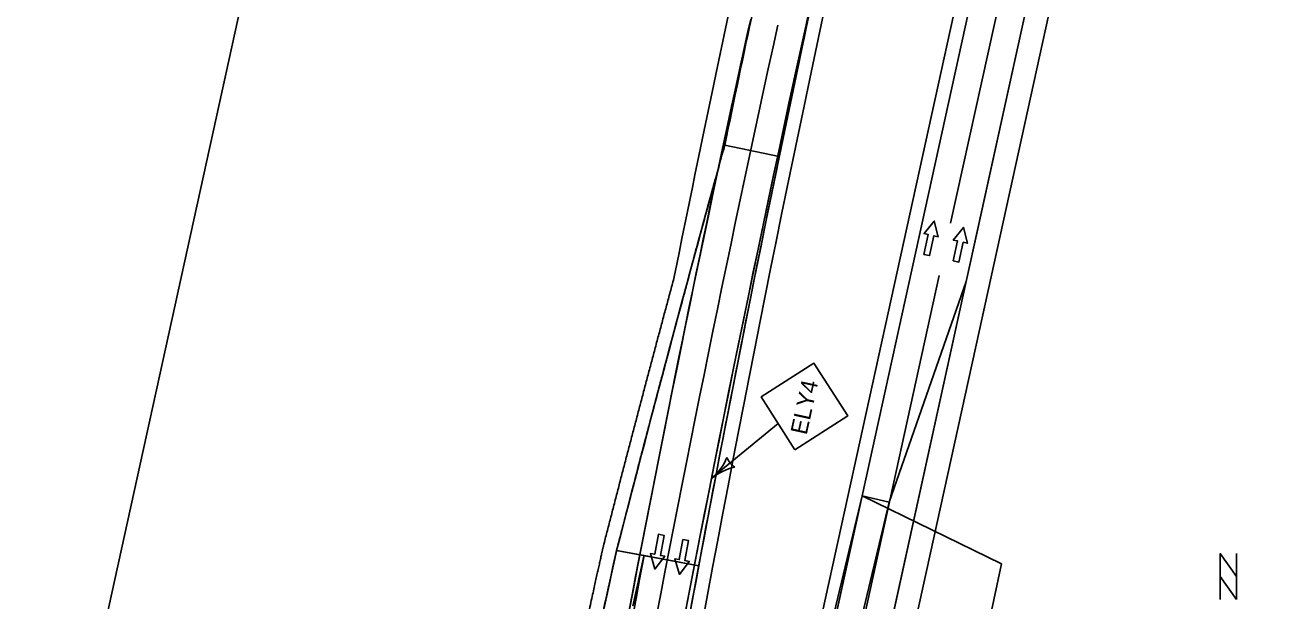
# Model space of a CAD drawing. Extents: x 14104283 to 14120882, y 8635219 to 8671666.
# Drawn here: x 14107791 to 14108331, y 8640647 to 8640895 of the extents above; entities that cross this region are included whole.
import ezdxf

# ---------------------------------------------------------------- set-up
doc = ezdxf.new("R2010")
doc.units = 0
for name, color, linetype in [('Cell', 7, 'Continuous'), ('dsnCellsNorthArrow', 7, 'Continuous'), ('dsnNonPlotable', 7, 'Continuous'), ('dsnPaintExistingBrokenLaneLineWhite', 7, 'Continuous'), ('dsnPaintExistingEdgeLineLeftYellow', 7, 'Continuous'), ('dsnPaintExistingEdgeLineRightWhite', 7, 'Continuous'), ('dsnPaintPlaceBrokenLaneLineWhite', 7, 'Continuous'), ('dsnPaintPlaceEdgeLineLeftYellow', 7, 'Continuous'), ('dsnPaintPlaceEdgeLineRightWhite', 7, 'Continuous'), ('dsnShadingPaved', 7, 'Continuous'), ('dsnStdLabel', 7, 'Continuous'), ('dsnStgShadingPrevPav', 7, 'Continuous'), ('dsnTapeRemoveChannelizingWhite', 7, 'Continuous'), ('dsnTapeRemoveChannelizingYellow', 7, 'Continuous'), ('Text', 7, 'Continuous')]:
    doc.layers.add(name, color=color, linetype=linetype)

msp = doc.modelspace()

# ---------------------------------------------------------------- linework, layer by layer
at = {"layer": 'Cell'}
for points in [[(14108180.75, 8640796.06), (14108178.31, 8640796.6), (14108180.19, 8640805.14), (14108178.36, 8640805.55), (14108182.76, 8640810.98), (14108184.46, 8640804.2), (14108182.63, 8640804.61)], [(14108193.37, 8640793.29), (14108190.92, 8640793.83), (14108192.81, 8640802.37), (14108190.98, 8640802.78), (14108195.38, 8640808.21), (14108197.08, 8640801.43), (14108195.25, 8640801.83)], [(14108063.89, 8640675.97), (14108066.35, 8640675.52), (14108064.79, 8640666.91), (14108066.63, 8640666.58), (14108062.44, 8640660.99), (14108060.48, 8640667.69), (14108062.33, 8640667.36)], [(14108074.46, 8640673.7), (14108076.92, 8640673.25), (14108075.36, 8640664.64), (14108077.2, 8640664.31), (14108073.01, 8640658.72), (14108071.05, 8640665.43), (14108072.9, 8640665.09)]]:
    msp.add_lwpolyline(points, close=True, dxfattribs=at)
for points in [[(14108182.63, 8640804.61), (14108184.46, 8640804.2), (14108182.76, 8640810.98), (14108178.36, 8640805.55), (14108180.19, 8640805.14), (14108178.31, 8640796.6), (14108180.75, 8640796.06), (14108182.63, 8640804.61)], [(14108195.25, 8640801.83), (14108197.08, 8640801.43), (14108195.38, 8640808.21), (14108190.98, 8640802.78), (14108192.81, 8640802.37), (14108190.92, 8640793.83), (14108193.37, 8640793.29), (14108195.25, 8640801.83)], [(14108062.33, 8640667.36), (14108060.48, 8640667.69), (14108062.44, 8640660.99), (14108066.63, 8640666.58), (14108064.79, 8640666.91), (14108066.35, 8640675.52), (14108063.89, 8640675.97), (14108062.33, 8640667.36)], [(14108072.9, 8640665.09), (14108071.05, 8640665.43), (14108073.01, 8640658.72), (14108077.2, 8640664.31), (14108075.36, 8640664.64), (14108076.92, 8640673.25), (14108074.46, 8640673.7), (14108072.9, 8640665.09)]]:
    msp.add_lwpolyline(points, dxfattribs=at)
at = {"layer": 'dsnCellsNorthArrow'}
msp.add_lwpolyline([(14108313, 8640647.95), (14108305.96, 8640657.81), (14108305.96, 8640667.66), (14108313, 8640657.81)], close=True, dxfattribs=at)
msp.add_lwpolyline([(14108305.96, 8640647.95), (14108305.96, 8640667.66), (14108313, 8640657.81), (14108313, 8640667.66)], dxfattribs=at)
at = {"layer": 'dsnNonPlotable'}
msp.add_lwpolyline([(14107651.31, 8639844.94), (14107987.7, 8641375.92), (14108480.93, 8641267.54), (14108144.54, 8639736.56)], close=True, dxfattribs=at)
at = {"layer": 'dsnPaintExistingBrokenLaneLineWhite'}
msp.add_line((14108189.82, 8640810.08), (14108306.37, 8641340.66), dxfattribs=at)
msp.add_arc((14117394.14, 8638857.08), 9500, 167.610212, 171.325989, dxfattribs=at)
at = {"layer": 'dsnPaintExistingEdgeLineLeftYellow'}
msp.add_line((14108151.72, 8640692.57), (14108199.55, 8640910.32), dxfattribs=at)
at = {"layer": 'dsnPaintExistingEdgeLineRightWhite'}
for p, q in [((14108201.57, 8640807.63), (14108723.98, 8643185.75)), ((14108196.58, 8640784.95), (14108201.57, 8640807.63))]:
    msp.add_line(p, q, dxfattribs=at)
for centre, radius, start, end in [((14117394.14, 8638857.08), 9512, 167.610212, 168.003119), ((14117245.13, 8638308.71), 9497.18, 164.578206, 165.609485), ((14117342.69, 8638609.63), 9522.13, 167.509575, 168.915877)]:
    msp.add_arc(centre, radius, start, end, dxfattribs=at)
at = {"layer": 'dsnPaintPlaceBrokenLaneLineWhite'}
msp.add_line((14108099.08, 8640397.01), (14108184.86, 8640787.53), dxfattribs=at)
at = {"layer": 'dsnPaintPlaceEdgeLineLeftYellow'}
msp.add_line((14108129.2, 8640590.05), (14108151.72, 8640692.57), dxfattribs=at)
msp.add_arc((14117502.5, 8638839.63), 9597.75, 167.26751, 171.3206, dxfattribs=at)
at = {"layer": 'dsnPaintPlaceEdgeLineRightWhite'}
msp.add_line((14108110.8, 8640394.44), (14108196.58, 8640784.95), dxfattribs=at)
at = {"layer": 'dsnShadingPaved'}
for p, q in [((14108723.98, 8643185.75), (14108196.58, 8640784.95)), ((14108151.72, 8640692.57), (14108294.65, 8641343.23)), ((14108196.58, 8640784.95), (14108163.38, 8640689.76)), ((14108163.38, 8640689.76), (14108151.72, 8640692.57))]:
    msp.add_line(p, q, dxfattribs=at)
msp.add_lwpolyline([(14108083.12, 8640400.52), (14108129.2, 8640590.05), (14108151.72, 8640692.57), (14108163.38, 8640689.76), (14108196.58, 8640784.95), (14108110.8, 8640394.44)], close=True, dxfattribs=at)
for centre, radius, start, end in [((14117502.5, 8638839.63), 9597.75, 167.266653, 171.3206), ((14117394.14, 8638857.08), 9512, 167.610212, 171.325989), ((14117394.14, 8638857.08), 9500, 167.610212, 171.325989), ((14117394.14, 8638857.08), 9500, 167.610212, 171.325989), ((14117502.5, 8638839.63), 9621.75, 168.048489, 169.460498), ((14117245.13, 8638308.71), 9497.18, 164.591267, 165.609485), ((14117342.69, 8638609.63), 9522.13, 167.509575, 168.915877)]:
    msp.add_arc(centre, radius, start, end, dxfattribs=at)
at = {"layer": 'dsnStdLabel'}
msp.add_line((14108115.47, 8640723.79), (14108086.85, 8640700.1), dxfattribs=at)
msp.add_lwpolyline([(14108122.75, 8640712.41), (14108145.49, 8640726.96), (14108130.94, 8640749.71), (14108108.2, 8640735.16)], close=True, dxfattribs=at)
for centre, radius, start, end in [((14108072.21, 8640717.78), 22.95, 309.6084, 337.6796), ((14108101.67, 8640712.36), 8.86, 201.8742, 237.3427), ((14108101.48, 8640682.41), 22.95, 101.5372, 129.6085)]:
    msp.add_arc(centre, radius, start, end, dxfattribs=at)
at = {"layer": 'dsnStgShadingPrevPav'}
for p, q in [((14108092.51, 8640843.67), (14108116.01, 8640838.82)), ((14108116.01, 8640838.82), (14108092.51, 8640843.67)), ((14108045.92, 8640669.04), (14108057.72, 8640666.84)), ((14108081.31, 8640662.43), (14108045.92, 8640669.04)), ((14108057.72, 8640666.84), (14108081.31, 8640662.43))]:
    msp.add_line(p, q, dxfattribs=at)
msp.add_lwpolyline([(14108081.5, 8640400.87), (14108123.34, 8640591.33), (14108126.55, 8640605.98), (14108216.67, 8641016.2), (14108268.16, 8641250.61), (14108382.95, 8641773.15), (14108422.02, 8641764.57), (14108309.38, 8641251.8), (14108270.22, 8641073.55), (14108265.93, 8641054.01), (14108255.74, 8641007.62), (14108202.1, 8640763.44), (14108120.56, 8640392.29)], close=True, dxfattribs=at)
for radius, start, end in [(9522, 167.610212, 168.688952), (9512, 167.610212, 168.328257), (9512, 167.610212, 168.328257), (9488, 167.610212, 172.222077), (9482, 167.610212, 172.222077), (9488, 167.610212, 168.328257), (9488, 168.328257, 169.413861), (9512, 169.413861, 172.222077), (9488, 169.413861, 172.222077), (9512, 169.413861, 170.574102)]:
    msp.add_arc((14117407.82, 8638919.35), radius, start, end, dxfattribs=at)
for points, degree in [([(14108045.92, 8640669.04), (14108046.67, 8640671.96), (14108048.17, 8640677.8), (14108050.43, 8640686.55), (14108052.7, 8640695.31), (14108054.98, 8640704.06), (14108057.26, 8640712.8), (14108059.55, 8640721.55), (14108061.85, 8640730.29), (14108064.16, 8640739.03), (14108066.48, 8640747.76), (14108068.81, 8640756.5), (14108071.14, 8640765.23), (14108073.48, 8640773.95), (14108075.83, 8640782.68), (14108078.19, 8640791.4), (14108080.55, 8640800.12), (14108082.93, 8640808.84), (14108085.31, 8640817.55), (14108087.7, 8640826.26), (14108090.1, 8640834.97), (14108091.7, 8640840.77), (14108092.51, 8640843.67)], 3), ([(14108045.92, 8640669.04), (14108046.67, 8640671.96), (14108048.17, 8640677.8), (14108050.43, 8640686.55), (14108052.7, 8640695.31), (14108054.98, 8640704.06), (14108057.26, 8640712.8), (14108059.55, 8640721.55), (14108061.85, 8640730.29), (14108064.16, 8640739.03), (14108066.48, 8640747.76), (14108068.81, 8640756.5), (14108071.14, 8640765.23), (14108073.48, 8640773.95), (14108075.83, 8640782.68), (14108078.19, 8640791.4), (14108080.55, 8640800.12), (14108082.93, 8640808.84), (14108085.31, 8640817.55), (14108087.7, 8640826.26), (14108090.1, 8640834.97), (14108091.7, 8640840.77), (14108092.51, 8640843.67)], 3), ([(14108070.77, 8640786.95), (14108070.25, 8640785.01), (14108069.2, 8640781.13), (14108067.63, 8640775.31), (14108066.07, 8640769.49), (14108064.51, 8640763.67), (14108062.96, 8640757.84), (14108061.41, 8640752.02), (14108059.86, 8640746.19), (14108058.31, 8640740.36), (14108056.77, 8640734.54), (14108055.23, 8640728.71), (14108053.7, 8640722.87), (14108052.17, 8640717.04), (14108050.64, 8640711.21), (14108049.12, 8640705.37), (14108047.6, 8640699.54), (14108046.09, 8640693.7), (14108044.58, 8640687.86), (14108043.07, 8640682.02), (14108041.56, 8640676.18), (14108040.56, 8640672.28), (14108040.06, 8640670.34)], 3), ([(14108040.07, 8640670.33), (14108039.11, 8640666.01), (14108035.79, 8640651.03), (14108029.85, 8640623.7), (14108025.19, 8640602.04), (14108020.26, 8640578.84), (14108015.47, 8640556.04), (14108010.72, 8640533.12), (14108006.03, 8640510.22), (14108001.39, 8640487.29), (14107996.81, 8640464.36), (14107992.28, 8640441.41), (14107987.82, 8640418.46), (14107983.4, 8640395.49), (14107979.05, 8640372.51), (14107974.75, 8640349.53), (14107970.51, 8640326.51), (14107966.33, 8640303.59), (14107962.15, 8640280.24), (14107958.29, 8640258.43), (14107953.48, 8640230.88), (14107950.9, 8640215.75), (14107950.15, 8640211.39)], 2), ([(14107956.07, 8640210.37), (14107957.38, 8640218.06), (14107960.02, 8640233.43), (14107964.04, 8640256.47), (14107968.11, 8640279.5), (14107972.24, 8640302.51), (14107976.42, 8640325.52), (14107980.66, 8640348.51), (14107984.96, 8640371.49), (14107989.32, 8640394.46), (14107993.73, 8640417.41), (14107998.19, 8640440.35), (14108002.71, 8640463.28), (14108007.29, 8640486.2), (14108011.92, 8640509.1), (14108016.61, 8640531.99), (14108021.36, 8640554.87), (14108026.16, 8640577.73), (14108031.01, 8640600.58), (14108035.93, 8640623.41), (14108040.89, 8640646.24), (14108044.25, 8640661.44), (14108045.92, 8640669.04)], 3), ([(14108045.17, 8640665.62), (14108045.34, 8640666.38), (14108045.5, 8640667.14), (14108045.67, 8640667.9)], 2), ([(14108045.67, 8640667.9), (14108045.76, 8640668.28), (14108045.84, 8640668.66), (14108045.92, 8640669.04)], 2), ([(14108043.91, 8640659.92), (14108044.16, 8640661.06), (14108044.41, 8640662.2), (14108044.67, 8640663.34)], 2), ([(14108044.67, 8640663.34), (14108044.75, 8640663.72), (14108044.83, 8640664.1), (14108044.92, 8640664.48)], 2), ([(14108044.92, 8640664.48), (14108045, 8640664.86), (14108045.09, 8640665.24), (14108045.17, 8640665.62)], 2), ([(14108056.71, 8640662.28), (14108056.46, 8640661.14), (14108056.21, 8640660), (14108055.96, 8640658.87)], 2), ([(14108055.96, 8640658.87), (14108056.21, 8640660), (14108056.46, 8640661.14), (14108056.71, 8640662.28)], 2), ([(14108056.97, 8640663.42), (14108056.88, 8640663.04), (14108056.8, 8640662.66), (14108056.71, 8640662.28)], 2), ([(14108056.71, 8640662.28), (14108056.8, 8640662.66), (14108056.88, 8640663.04), (14108056.97, 8640663.42)], 2), ([(14108057.22, 8640664.56), (14108057.13, 8640664.18), (14108057.05, 8640663.8), (14108056.97, 8640663.42)], 2), ([(14108056.97, 8640663.42), (14108057.05, 8640663.8), (14108057.13, 8640664.18), (14108057.22, 8640664.56)], 2), ([(14108057.47, 8640665.7), (14108057.38, 8640665.32), (14108057.3, 8640664.94), (14108057.22, 8640664.56)], 2), ([(14108057.22, 8640664.56), (14108057.3, 8640664.94), (14108057.38, 8640665.32), (14108057.47, 8640665.7)], 2), ([(14108057.72, 8640666.84), (14108057.64, 8640666.46), (14108057.55, 8640666.08), (14108057.47, 8640665.7)], 2), ([(14108057.47, 8640665.7), (14108057.55, 8640666.08), (14108057.64, 8640666.46), (14108057.72, 8640666.84)], 2), ([(14108042.91, 8640655.36), (14108043.07, 8640656.12), (14108043.24, 8640656.88), (14108043.41, 8640657.64)], 2), ([(14108043.41, 8640657.64), (14108043.49, 8640658.02), (14108043.58, 8640658.4), (14108043.66, 8640658.78)], 2), ([(14108043.66, 8640658.78), (14108043.74, 8640659.16), (14108043.83, 8640659.54), (14108043.91, 8640659.92)], 2), ([(14108055.71, 8640657.73), (14108055.21, 8640655.45), (14108054.7, 8640653.17), (14108054.2, 8640650.89)], 2), ([(14108054.2, 8640650.89), (14108054.7, 8640653.17), (14108055.21, 8640655.45), (14108055.71, 8640657.73)], 2), ([(14108055.96, 8640658.87), (14108055.88, 8640658.49), (14108055.79, 8640658.11), (14108055.71, 8640657.73)], 2), ([(14108055.71, 8640657.73), (14108055.79, 8640658.11), (14108055.88, 8640658.49), (14108055.96, 8640658.87)], 2), ([(14108041.9, 8640650.8), (14108041.99, 8640651.18), (14108042.07, 8640651.56), (14108042.15, 8640651.94)], 2), ([(14108042.15, 8640651.94), (14108042.4, 8640653.08), (14108042.65, 8640654.22), (14108042.91, 8640655.36)], 2), ([(14108040.9, 8640646.23), (14108040.98, 8640646.61), (14108041.07, 8640646.99), (14108041.15, 8640647.37)], 2), ([(14108041.15, 8640647.37), (14108041.23, 8640647.76), (14108041.32, 8640648.14), (14108041.4, 8640648.52)], 2), ([(14108041.4, 8640648.52), (14108041.48, 8640648.9), (14108041.57, 8640649.28), (14108041.65, 8640649.66)], 2), ([(14108041.65, 8640649.66), (14108041.74, 8640650.04), (14108041.82, 8640650.42), (14108041.9, 8640650.8)], 2), ([(14108053.45, 8640647.48), (14108053.29, 8640646.72), (14108053.12, 8640645.96), (14108052.95, 8640645.2)], 2), ([(14108052.95, 8640645.2), (14108053.12, 8640645.96), (14108053.29, 8640646.72), (14108053.45, 8640647.48)], 2), ([(14108053.7, 8640648.62), (14108053.62, 8640648.24), (14108053.54, 8640647.86), (14108053.45, 8640647.48)], 2), ([(14108053.45, 8640647.48), (14108053.54, 8640647.86), (14108053.62, 8640648.24), (14108053.7, 8640648.62)], 2), ([(14108053.95, 8640649.75), (14108053.87, 8640649.37), (14108053.79, 8640648.99), (14108053.7, 8640648.62)], 2), ([(14108053.7, 8640648.62), (14108053.79, 8640648.99), (14108053.87, 8640649.37), (14108053.95, 8640649.75)], 2), ([(14108054.2, 8640650.89), (14108054.12, 8640650.51), (14108054.04, 8640650.13), (14108053.95, 8640649.75)], 2), ([(14108053.95, 8640649.75), (14108054.04, 8640650.13), (14108054.12, 8640650.51), (14108054.2, 8640650.89)], 2)]:
    msp.add_open_spline(points, degree=degree, dxfattribs=at)
at = {"layer": 'dsnTapeRemoveChannelizingWhite'}
for p, q in [((14108163.38, 8640689.76), (14108196.58, 8640784.95)), ((14108093.19, 8640398.18), (14108163.38, 8640689.76))]:
    msp.add_line(p, q, dxfattribs=at)
at = {"layer": 'dsnTapeRemoveChannelizingYellow'}
msp.add_line((14108081.5, 8640400.87), (14108151.72, 8640692.57), dxfattribs=at)
at = {"layer": 'Text'}
msp.add_lwpolyline([(14108198.5, 8640601.19), (14108211.73, 8640663.2), (14108151.72, 8640692.57)], dxfattribs=at)

# ---------------------------------------------------------------- texts
at = {"layer": 'dsnStdLabel'}
msp.add_text('ELY4', height=7.2, rotation=77.6078, dxfattribs=at).set_placement((14108127.77, 8640718.51))

doc.saveas('drawing.dxf')
